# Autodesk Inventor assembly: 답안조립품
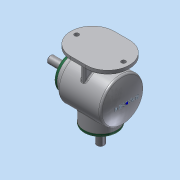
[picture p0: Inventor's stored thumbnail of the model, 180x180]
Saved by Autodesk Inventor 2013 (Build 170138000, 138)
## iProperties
Created: 2016-04
Part Number: 답안조립품
Document SubType Name: Assembly
Designer: dgall
Author: dgall
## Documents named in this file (14)
- C:\Users\dgall\Desktop\460407V1004\답안조립품.iam
- C:\Users\dgall\Desktop\460407V1004\본체.ipt
- C:\Users\dgall\Desktop\460407V1004\메인 축.ipt
- 메인 축.ipt
- C:\Users\dgall\Desktop\460407V1004\베어링 6203.ipt
- C:\Users\dgall\Desktop\460407V1004\오일실 17 32 8.ipt
- C:\Users\dgall\Desktop\460407V1004\커버.ipt
- C:\Users\dgall\Desktop\460407V1004\메인 베벨기어.ipt
- C:\Users\dgall\Desktop\460407V1004\키 5x5.ipt
- C:\Users\dgall\Desktop\460407V1004\서브 베벨기어.ipt
- C:\Users\dgall\Desktop\460407V1004\서브 축.ipt
- 서브 축.ipt
- C:\Users\dgall\Desktop\460407V1004\키 4x4.ipt
- C:\Users\dgall\Desktop\460407V1004\M4.ipt
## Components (8 placed, 1 different names)
1. M4:1
2. M4:2
3. M4:3
4. M4:4
5. M4:5
6. M4:6
7. M4:7
8. M4:8
